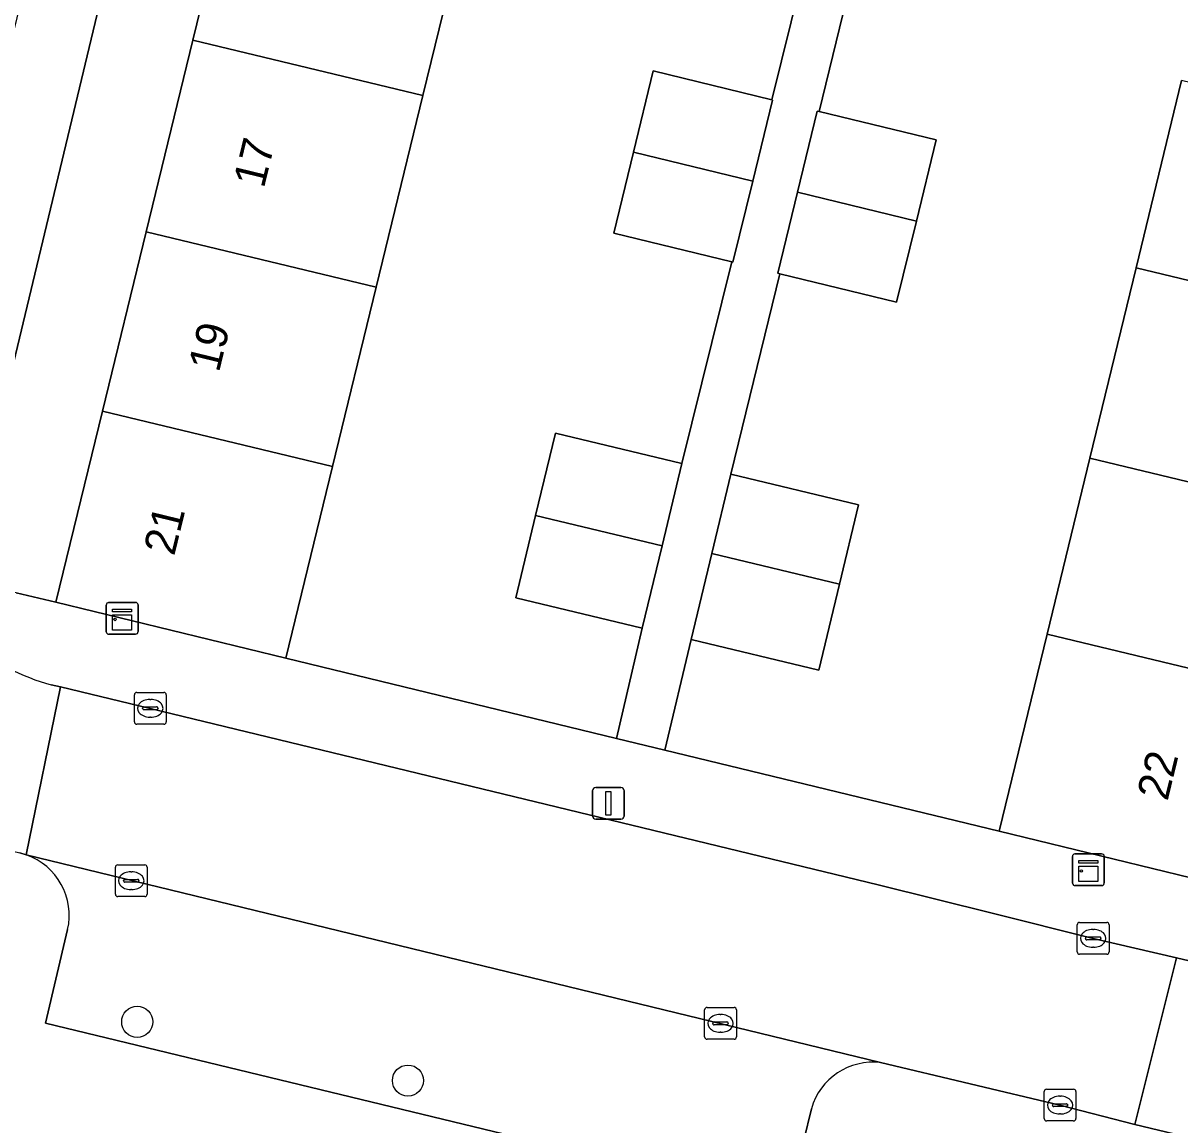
# Model space of a CAD drawing. Extents: x 162803 to 163818, y 381639 to 382475.
# Drawn here: x 163276.24 to 163312.66, y 382193.93 to 382228.61 of the extents above; entities that cross this region are included whole.
import ezdxf

# ---------------------------------------------------------------- set-up
doc = ezdxf.new("R2010")
doc.units = 0
for name, color, linetype in [('IMGEO_Boom', 7, 'Continuous'), ('IMGEO_Erf', 7, 'Continuous'), ('IMGEO_Kast', 7, 'Continuous'), ('IMGEO_Kolk', 7, 'Continuous'), ('IMGEO_Lichtmast', 7, 'Continuous'), ('IMGEO_Pand', 7, 'Continuous'), ('IMGEO_Pand_nummerreeks', 7, 'Continuous'), ('IMGEO_Parkeervlak_open', 7, 'Continuous'), ('IMGEO_Rijbaan_lokaal_open', 7, 'Continuous'), ('IMGEO_Voetpad_open', 7, 'Continuous')]:
    doc.layers.add(name, color=color, linetype=linetype)

msp = doc.modelspace()

# ---------------------------------------------------------------- linework, layer by layer
at = {"layer": 'IMGEO_Boom'}
for centre in [(163279.832, 382197.169), (163288.356, 382195.321)]:
    msp.add_circle(centre, 0.489, dxfattribs=at)
at = {"layer": 'IMGEO_Erf'}
for points in [[(163276.021, 382210.678), (163277.269, 382210.381), (163278.736, 382216.394), (163280.113, 382222.037), (163281.586, 382228.075), (163282.998, 382233.864), (163284.339, 382239.358), (163285.788, 382245.299), (163286.935, 382250), (163287.154, 382250.896), (163288.615, 382256.885), (163289.992, 382262.529), (163291.429, 382268.42), (163292.829, 382274.157), (163289.642, 382275.033), (163283.634, 382250), (163274.71, 382212.82)], [(163290.242, 382232.12), (163288.829, 382226.332), (163287.356, 382220.293), (163285.979, 382214.651), (163284.507, 382208.616), (163294.926, 382206.09), (163295.732, 382209.562), (163291.751, 382210.52), (163292.374, 382213.112), (163292.997, 382215.701), (163296.979, 382214.743), (163298.55, 382221.089), (163294.835, 382221.995), (163295.458, 382224.547), (163296.08, 382227.1), (163299.812, 382226.189), (163301.335, 382232.341)], [(163302.806, 382231.982), (163301.306, 382225.824), (163304.983, 382224.928), (163304.361, 382222.376), (163303.738, 382219.824), (163300.061, 382220.72), (163298.523, 382214.409), (163302.545, 382213.441), (163301.944, 382210.943), (163301.294, 382208.24), (163297.272, 382209.208), (163296.438, 382205.724), (163306.972, 382203.17), (163308.478, 382209.37), (163309.826, 382214.914), (163311.282, 382220.906), (163312.713, 382226.799)]]:
    msp.add_lwpolyline(points, dxfattribs=at)
at = {"layer": 'IMGEO_Kast'}
for p, q in [((163278.858, 382209.446), (163278.858, 382210.287)), ((163278.858, 382210.287), (163278.858, 382209.446)), ((163278.933, 382210.371), (163279.774, 382210.371)), ((163279.774, 382210.371), (163278.933, 382210.371)), ((163279.858, 382210.296), (163279.858, 382209.455)), ((163279.858, 382209.455), (163279.858, 382210.296)), ((163279.783, 382209.371), (163278.942, 382209.371)), ((163278.942, 382209.371), (163279.783, 382209.371)), ((163309.277, 382201.532), (163309.277, 382202.373)), ((163309.277, 382202.373), (163309.277, 382201.532)), ((163309.352, 382202.457), (163310.193, 382202.457)), ((163310.193, 382202.457), (163309.352, 382202.457)), ((163310.277, 382202.382), (163310.277, 382201.541)), ((163310.277, 382201.541), (163310.277, 382202.382)), ((163310.202, 382201.457), (163309.361, 382201.457)), ((163309.361, 382201.457), (163310.202, 382201.457))]:
    msp.add_line(p, q, dxfattribs=at)
for points in [[(163279.053, 382210.161), (163279.653, 382210.161), (163279.653, 382210.076), (163279.053, 382210.076), (163279.053, 382210.161)], [(163279.053, 382209.986), (163279.653, 382209.986), (163279.653, 382209.497), (163279.053, 382209.497), (163279.053, 382209.986)], [(163309.472, 382202.247), (163310.072, 382202.247), (163310.072, 382202.162), (163309.472, 382202.162), (163309.472, 382202.247)], [(163309.472, 382202.072), (163310.072, 382202.072), (163310.072, 382201.583), (163309.472, 382201.583), (163309.472, 382202.072)]]:
    msp.add_lwpolyline(points, dxfattribs=at)
for centre in [(163279.137, 382209.835), (163309.556, 382201.921)]:
    msp.add_circle(centre, 0.0377, dxfattribs=at)
for centre, start, end in [((163278.936, 382210.293), 92.4484, 184.2845), ((163278.936, 382210.293), 92.4484, 184.2845), ((163279.78, 382210.293), 2.4484, 94.2845), ((163279.78, 382210.293), 2.4484, 94.2845), ((163278.936, 382209.449), 182.4484, 274.2845), ((163278.936, 382209.449), 182.4484, 274.2845), ((163279.78, 382209.449), 272.4484, 4.2845), ((163279.78, 382209.449), 272.4484, 4.2845), ((163309.355, 382202.379), 92.4484, 184.2845), ((163309.355, 382202.379), 92.4484, 184.2845), ((163310.199, 382202.379), 2.4484, 94.2845), ((163310.199, 382202.379), 2.4484, 94.2845), ((163309.355, 382201.535), 182.4484, 274.2845), ((163309.355, 382201.535), 182.4484, 274.2845), ((163310.199, 382201.535), 272.4484, 4.2845), ((163310.199, 382201.535), 272.4484, 4.2845)]:
    msp.add_arc(centre, 0.0779, start, end, dxfattribs=at)
at = {"layer": 'IMGEO_Kolk'}
for p, q in [((163279.744, 382206.613), (163279.744, 382207.465)), ((163279.819, 382207.539), (163280.671, 382207.539)), ((163280.232, 382207.319), (163280.257, 382207.319)), ((163280.745, 382207.465), (163280.745, 382206.613)), ((163280.003, 382207.033), (163280.003, 382207.045)), ((163280.441, 382206.996), (163280.043, 382206.996)), ((163280.046, 382207.082), (163280.444, 382207.082)), ((163280.487, 382207.045), (163280.487, 382207.033)), ((163280.255, 382206.759), (163280.23, 382206.759)), ((163280.671, 382206.539), (163279.819, 382206.539)), ((163279.145, 382201.186), (163279.145, 382202.038)), ((163279.22, 382202.112), (163280.072, 382202.112)), ((163279.633, 382201.892), (163279.658, 382201.892)), ((163280.146, 382202.038), (163280.146, 382201.186)), ((163279.404, 382201.606), (163279.404, 382201.618)), ((163279.842, 382201.569), (163279.444, 382201.569)), ((163279.447, 382201.655), (163279.845, 382201.655)), ((163279.888, 382201.618), (163279.888, 382201.606)), ((163280.072, 382201.112), (163279.22, 382201.112)), ((163279.656, 382201.332), (163279.631, 382201.332)), ((163309.427, 382199.372), (163309.427, 382200.224)), ((163309.502, 382200.298), (163310.354, 382200.298)), ((163309.915, 382200.078), (163309.94, 382200.078)), ((163310.428, 382200.224), (163310.428, 382199.372)), ((163309.686, 382199.792), (163309.686, 382199.804)), ((163310.124, 382199.755), (163309.726, 382199.755)), ((163309.729, 382199.841), (163310.127, 382199.841)), ((163310.17, 382199.804), (163310.17, 382199.792)), ((163310.354, 382199.298), (163309.502, 382199.298)), ((163309.938, 382199.518), (163309.913, 382199.518)), ((163297.696, 382196.696), (163297.696, 382197.548)), ((163297.771, 382197.622), (163298.623, 382197.622)), ((163298.697, 382197.548), (163298.697, 382196.696)), ((163297.955, 382197.116), (163297.955, 382197.128)), ((163297.998, 382197.165), (163298.396, 382197.165)), ((163298.184, 382197.402), (163298.209, 382197.402)), ((163298.439, 382197.128), (163298.439, 382197.116)), ((163298.393, 382197.079), (163297.995, 382197.079)), ((163298.207, 382196.842), (163298.182, 382196.842)), ((163298.623, 382196.622), (163297.771, 382196.622)), ((163308.385, 382194.123), (163308.385, 382194.975)), ((163308.46, 382195.049), (163309.312, 382195.049)), ((163309.386, 382194.975), (163309.386, 382194.123)), ((163308.644, 382194.543), (163308.644, 382194.555)), ((163308.687, 382194.592), (163309.085, 382194.592)), ((163308.873, 382194.829), (163308.898, 382194.829)), ((163309.128, 382194.555), (163309.128, 382194.543)), ((163309.082, 382194.506), (163308.684, 382194.506)), ((163308.896, 382194.269), (163308.871, 382194.269)), ((163309.312, 382194.049), (163308.46, 382194.049))]:
    msp.add_line(p, q, dxfattribs=at)
for points in [[(163279.744, 382206.613), (163279.744, 382207.465)], [(163279.819, 382207.539), (163280.671, 382207.539)], [(163280.745, 382207.465), (163280.745, 382206.613)], [(163280.671, 382206.539), (163279.819, 382206.539)], [(163279.145, 382201.186), (163279.145, 382202.038)], [(163279.22, 382202.112), (163280.072, 382202.112)], [(163280.146, 382202.038), (163280.146, 382201.186)], [(163280.072, 382201.112), (163279.22, 382201.112)], [(163309.427, 382199.372), (163309.427, 382200.224)], [(163309.502, 382200.298), (163310.354, 382200.298)], [(163310.428, 382200.224), (163310.428, 382199.372)], [(163310.354, 382199.298), (163309.502, 382199.298)], [(163297.696, 382196.696), (163297.696, 382197.548)], [(163297.771, 382197.622), (163298.623, 382197.622)], [(163298.697, 382197.548), (163298.697, 382196.696)], [(163298.623, 382196.622), (163297.771, 382196.622)], [(163308.385, 382194.123), (163308.385, 382194.975)], [(163308.46, 382195.049), (163309.312, 382195.049)], [(163309.386, 382194.975), (163309.386, 382194.123)], [(163309.312, 382194.049), (163308.46, 382194.049)]]:
    msp.add_lwpolyline(points, dxfattribs=at)
for centre, radius, start, end in [((163279.821, 382207.463), 0.0765, 91.552, 178.448), ((163279.821, 382207.463), 0.0765, 91.552, 178.448), ((163280.669, 382207.463), 0.0765, 1.552, 88.448), ((163280.669, 382207.463), 0.0765, 1.552, 88.448), ((163280.043, 382207.042), 0.0403, 85.8775, 175.7526), ((163280.04, 382207.032), 0.0366, 178.938, 274.7102), ((163280.444, 382207.039), 0.043, 264.8664, 352.4533), ((163280.448, 382207.044), 0.0386, 1.7309, 96.639), ((163279.821, 382206.615), 0.0765, 181.552, 268.448), ((163279.821, 382206.615), 0.0765, 181.552, 268.448), ((163280.669, 382206.615), 0.0765, 271.552, 358.448), ((163280.669, 382206.615), 0.0765, 271.552, 358.448), ((163279.222, 382202.036), 0.0765, 91.552, 178.448), ((163279.222, 382202.036), 0.0765, 91.552, 178.448), ((163280.07, 382202.036), 0.0765, 1.552, 88.448), ((163280.07, 382202.036), 0.0765, 1.552, 88.448), ((163279.444, 382201.615), 0.0403, 85.8775, 175.7526), ((163279.441, 382201.605), 0.0366, 178.938, 274.7102), ((163279.845, 382201.612), 0.043, 264.8664, 352.4533), ((163279.849, 382201.617), 0.0386, 1.7309, 96.639), ((163279.222, 382201.188), 0.0765, 181.552, 268.448), ((163279.222, 382201.188), 0.0765, 181.552, 268.448), ((163280.07, 382201.188), 0.0765, 271.552, 358.448), ((163280.07, 382201.188), 0.0765, 271.552, 358.448), ((163309.504, 382200.222), 0.0765, 91.552, 178.448), ((163309.504, 382200.222), 0.0765, 91.552, 178.448), ((163310.352, 382200.222), 0.0765, 1.552, 88.448), ((163310.352, 382200.222), 0.0765, 1.552, 88.448), ((163309.726, 382199.801), 0.0403, 85.8775, 175.7526), ((163309.723, 382199.791), 0.0366, 178.938, 274.7102), ((163310.127, 382199.798), 0.043, 264.8664, 352.4533), ((163310.131, 382199.803), 0.0386, 1.7309, 96.639), ((163309.504, 382199.374), 0.0765, 181.552, 268.448), ((163309.504, 382199.374), 0.0765, 181.552, 268.448), ((163310.352, 382199.374), 0.0765, 271.552, 358.448), ((163310.352, 382199.374), 0.0765, 271.552, 358.448), ((163297.773, 382197.546), 0.0765, 91.552, 178.448), ((163297.773, 382197.546), 0.0765, 91.552, 178.448), ((163298.621, 382197.546), 0.0765, 1.552, 88.448), ((163298.621, 382197.546), 0.0765, 1.552, 88.448), ((163297.995, 382197.125), 0.0403, 85.8775, 175.7526), ((163297.992, 382197.115), 0.0366, 178.938, 274.7102), ((163298.396, 382197.122), 0.043, 264.8664, 352.4533), ((163298.4, 382197.127), 0.0386, 1.7309, 96.639), ((163297.773, 382196.698), 0.0765, 181.552, 268.448), ((163297.773, 382196.698), 0.0765, 181.552, 268.448), ((163298.621, 382196.698), 0.0765, 271.552, 358.448), ((163298.621, 382196.698), 0.0765, 271.552, 358.448), ((163308.462, 382194.973), 0.0765, 91.552, 178.448), ((163308.462, 382194.973), 0.0765, 91.552, 178.448), ((163309.31, 382194.973), 0.0765, 1.552, 88.448), ((163309.31, 382194.973), 0.0765, 1.552, 88.448), ((163308.684, 382194.552), 0.0403, 85.8775, 175.7526), ((163308.681, 382194.542), 0.0366, 178.938, 274.7102), ((163309.085, 382194.549), 0.043, 264.8664, 352.4533), ((163309.089, 382194.554), 0.0386, 1.7309, 96.639), ((163308.462, 382194.125), 0.0765, 181.552, 268.448), ((163308.462, 382194.125), 0.0765, 181.552, 268.448), ((163309.31, 382194.125), 0.0765, 271.552, 358.448), ((163309.31, 382194.125), 0.0765, 271.552, 358.448)]:
    msp.add_arc(centre, radius, start, end, dxfattribs=at)
for centre, major_axis, ratio, start_param, end_param in [((163280.231, 382207.039), (-0.387, 0.002), 0.722429, 4.712389, 7.853982), ((163280.256, 382207.039), (-0.39, 0.002), 0.717154, 1.570796, 4.712389), ((163279.632, 382201.612), (-0.387, 0.002), 0.722429, 4.712389, 7.853982), ((163279.657, 382201.612), (-0.39, 0.002), 0.717154, 1.570796, 4.712389), ((163309.914, 382199.798), (-0.387, 0.002), 0.722429, 4.712389, 7.853982), ((163309.939, 382199.798), (-0.39, 0.002), 0.717154, 1.570796, 4.712389), ((163298.183, 382197.122), (-0.387, 0.002), 0.722429, 4.712389, 7.853982), ((163298.208, 382197.122), (-0.39, 0.002), 0.717154, 1.570796, 4.712389), ((163308.872, 382194.549), (-0.387, 0.002), 0.722429, 4.712389, 7.853982), ((163308.897, 382194.549), (-0.39, 0.002), 0.717154, 1.570796, 4.712389)]:
    msp.add_ellipse(centre, major_axis=major_axis, ratio=ratio, start_param=start_param, end_param=end_param, dxfattribs=at)
at = {"layer": 'IMGEO_Lichtmast'}
for p, q in [((163294.17, 382203.647), (163294.17, 382204.447)), ((163294.17, 382204.447), (163294.17, 382203.647)), ((163294.27, 382204.547), (163295.06, 382204.547)), ((163295.06, 382204.547), (163294.27, 382204.547)), ((163295.16, 382204.447), (163295.16, 382203.647)), ((163295.16, 382203.647), (163295.16, 382204.447)), ((163295.06, 382203.547), (163294.27, 382203.547)), ((163294.27, 382203.547), (163295.06, 382203.547))]:
    msp.add_line(p, q, dxfattribs=at)
msp.add_lwpolyline([(163294.59, 382204.422), (163294.74, 382204.422), (163294.74, 382203.672), (163294.59, 382203.672), (163294.59, 382204.422)], dxfattribs=at)
for centre, start, end in [((163294.27, 382204.447), 90, 180), ((163294.27, 382204.447), 90, 180), ((163295.06, 382204.447), 0, 90), ((163295.06, 382204.447), 360, 90), ((163294.27, 382203.647), 180, 270), ((163294.27, 382203.647), 180, 270), ((163295.06, 382203.647), 270, 0), ((163295.06, 382203.647), 270, 0)]:
    msp.add_arc(centre, 0.1, start, end, dxfattribs=at)
at = {"layer": 'IMGEO_Pand'}
for points in [[(163282.998, 382233.864), (163281.586, 382228.075), (163288.829, 382226.332), (163290.242, 382232.12)], [(163280.113, 382222.037), (163287.356, 382220.293), (163288.829, 382226.332), (163281.586, 382228.075)], [(163299.812, 382226.189), (163296.08, 382227.1), (163295.458, 382224.547), (163299.21, 382223.632), (163299.832, 382226.184)], [(163318.52, 382219.162), (163319.952, 382225.055), (163312.713, 382226.799), (163311.282, 382220.906)], [(163301.306, 382225.824), (163301.242, 382225.84), (163300.619, 382223.288), (163304.361, 382222.376), (163304.983, 382224.928)], [(163299.21, 382223.632), (163295.458, 382224.547), (163294.835, 382221.995), (163298.55, 382221.089), (163298.587, 382221.08)], [(163304.361, 382222.376), (163300.619, 382223.288), (163299.997, 382220.736), (163300.061, 382220.72), (163303.738, 382219.824)], [(163287.356, 382220.293), (163280.113, 382222.037), (163278.736, 382216.394), (163285.979, 382214.651)], [(163318.52, 382219.162), (163311.282, 382220.906), (163309.826, 382214.914), (163317.064, 382213.17)], [(163285.979, 382214.651), (163278.736, 382216.394), (163277.269, 382210.381), (163284.507, 382208.616)], [(163292.374, 382213.112), (163296.356, 382212.154), (163296.979, 382214.743), (163292.997, 382215.701)], [(163309.826, 382214.914), (163308.478, 382209.37), (163315.717, 382207.627), (163317.064, 382213.17)], [(163297.922, 382211.912), (163301.944, 382210.943), (163302.545, 382213.441), (163298.523, 382214.409)], [(163292.374, 382213.112), (163291.751, 382210.52), (163295.732, 382209.562), (163296.356, 382212.154)], [(163297.922, 382211.912), (163297.272, 382209.208), (163301.294, 382208.24), (163301.944, 382210.943)], [(163315.717, 382207.627), (163308.478, 382209.37), (163306.972, 382203.17), (163314.205, 382201.406)]]:
    msp.add_lwpolyline(points, close=True, dxfattribs=at)
at = {"layer": 'IMGEO_Parkeervlak_open'}
for points in [[(163303.237, 382195.89), (163276.34, 382202.428)], [(163277.641, 382200.072), (163276.941, 382197.127), (163300.335, 382191.472), (163301.055, 382194.434)]]:
    msp.add_lwpolyline(points, dxfattribs=at)
for centre, radius, start, end in [((163275.664, 382200.517), 2.027, 347.3102, 70.5054), ((163303.008, 382193.869), 2.033, 83.5478, 163.8808)]:
    msp.add_arc(centre, radius, start, end, dxfattribs=at)
at = {"layer": 'IMGEO_Rijbaan_lokaal_open'}
for points in [[(163272.769, 382215.313), (163277.825, 382236.079), (163272.501, 382237.365), (163266.432, 382213.1), (163264.504, 382205.242), (163276.142, 382202.487), (163276.34, 382202.428), (163277.416, 382207.71)], [(163277.416, 382207.71), (163277.123, 382207.78)], [(163314.103, 382198.818), (163312.546, 382199.183), (163311.244, 382193.937), (163327.147, 382190.126), (163327.797, 382189.969), (163329, 382195.189), (163328.462, 382195.318)]]:
    msp.add_lwpolyline(points, dxfattribs=at)
msp.add_lwpolyline([(163303.157, 382201.486), (163280.241, 382207.038), (163277.416, 382207.71), (163276.34, 382202.428), (163303.237, 382195.89), (163308.883, 382194.55), (163311.244, 382193.937), (163312.546, 382199.183), (163309.924, 382199.797), (163306.787, 382200.578)], close=True, dxfattribs=at)
msp.add_arc((163278.678, 382213.705), 6.126, 201.9135, 255.2915, dxfattribs=at)
at = {"layer": 'IMGEO_Voetpad_open'}
for points in [[(163274.71, 382212.82), (163283.634, 382250)], [(163301.335, 382232.341), (163299.812, 382226.189), (163299.832, 382226.184), (163299.21, 382223.632), (163298.587, 382221.08), (163298.55, 382221.089), (163296.979, 382214.743), (163296.356, 382212.154), (163295.732, 382209.562), (163294.926, 382206.09), (163296.438, 382205.724), (163297.272, 382209.208), (163297.922, 382211.912), (163298.523, 382214.409), (163300.061, 382220.72), (163299.997, 382220.736), (163300.619, 382223.288), (163301.242, 382225.84), (163301.306, 382225.824), (163302.806, 382231.982)], [(163296.438, 382205.724), (163294.926, 382206.09), (163284.507, 382208.616), (163277.269, 382210.381), (163276.021, 382210.678), (163275.972, 382210.682), (163272.995, 382211.419)], [(163277.123, 382207.78), (163277.416, 382207.71), (163280.241, 382207.038), (163303.157, 382201.486), (163306.787, 382200.578), (163309.924, 382199.797), (163312.546, 382199.183), (163314.103, 382198.818)], [(163319.462, 382200.055), (163317.086, 382200.697), (163314.205, 382201.406), (163306.972, 382203.17), (163296.438, 382205.724)], [(163276.34, 382202.428), (163276.142, 382202.487)], [(163276.941, 382197.127), (163277.641, 382200.072)], [(163301.055, 382194.434), (163300.335, 382191.472), (163276.941, 382197.127)], [(163327.147, 382190.126), (163311.244, 382193.937), (163308.883, 382194.55), (163303.237, 382195.89)]]:
    msp.add_lwpolyline(points, dxfattribs=at)
for centre, radius, start, end in [((163278.678, 382213.705), 6.126, 201.9135, 255.2915), ((163275.664, 382200.517), 2.027, 347.3102, 70.5054), ((163303.008, 382193.869), 2.033, 83.5478, 163.8808)]:
    msp.add_arc(centre, radius, start, end, dxfattribs=at)

# ---------------------------------------------------------------- texts
at = {"layer": 'IMGEO_Pand_nummerreeks'}
for s, rotation, p in [('17', 76.2889, (163283.818, 382223.383)), ('19', 76.2889, (163282.403, 382217.585)), ('21', 76.2889, (163280.994, 382211.81)), ('22', 76.3426, (163312.266, 382204.095))]:
    msp.add_text(s, height=1, rotation=rotation, dxfattribs=at).set_placement(p)

doc.saveas('drawing.dxf')
